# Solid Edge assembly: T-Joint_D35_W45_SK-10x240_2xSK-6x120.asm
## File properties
Author: fknapp
Template: iso metric assembly.asm
Last saved by: fknapp
Revision: 6
Application: Solid Edge
Username: fknapp
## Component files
T-Joint_D35_W45.par
SK Schraube 6x120_ohne_Gewinde.par
SK Schraube 10x240_ohne_Gewinde_22042020.par
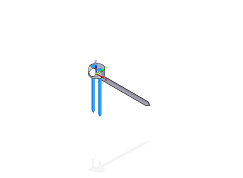
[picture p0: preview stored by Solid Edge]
